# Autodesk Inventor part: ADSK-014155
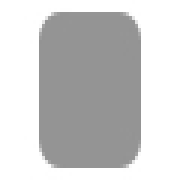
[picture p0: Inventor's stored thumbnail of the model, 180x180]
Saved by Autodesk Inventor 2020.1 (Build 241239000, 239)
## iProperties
Created: 2019-01
Part Number: ADSK-014155
Material: Stahl, weich
Document SubType Name: Modeling
Designer: lutzd
Language: de-DE
Size Designation: 5 x 39,384472 x 39,384472
Categories: <MemberInstance><Categories><Category DisplayName="Sonstige Bauteile" InternalName="5aa15e00-363f-49f2-933f-16f664388e3f" Mnemonic="OTHER"><Category DisplayName
Mass: 60.0398 g
Surface Area: 38.0412 cm^2
Volume: 7.64838 cm^3
Density: 7.85 g/cm^3
Appearance: Halbpoliert
Dimensions: 39,4x39,4x5 mm
Mass: 0,06 kg
DocNumber: ADSK-014155
Folder: 01 - Themengebiete\Simplification\01 - Packaging machine\
VDS_Category: 3D Komponenten
VDS_NumSchm: Autodesk
IsCustomPart: 1
Title: end cap
Author: lutzd
Revision Number: -
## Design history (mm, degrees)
sketch "Sketch1"
  geometry: L1 (0, 20.175)-(0, -21.446); L2 (-20.203, 0)-(20.169, 0); L3 (-19.692, 19.692)-(19.692, 19.692); L4 (19.692, 19.692)-(19.692, -19.692); L5 (19.692, -19.692)-(-19.692, -19.692); L6 (-19.692, -19.692)-(-19.692, 19.692); 1 further point
  constraints: 12 end point, 2 horizontal, 2 parallel, 2 point on line, 1 perpendicular, 1 vertical
  dimensions: "d0" = 39.38447 distance between parallel lines of L5 L3 (= height); "d1" = 19.69224 distance between parallel lines of L2 L3 (= 0.5 x height); "d2" = 39.38447 distance between parallel lines of L6 L4 (= width); "d3" = 19.69224 distance between parallel lines of L6 L1 (= 0.5 x width)
extrude "Extrusion1" new body sketch "Sketch1" distance "d4" = 5 (= thickness); taper "d5" = 0 deg
fillet "Fillet1" dims "d6" = 5 (= fillet), "d7" = 0, "fillet" = 5 [user parameter; used in 1 equation term]
chamfer "Chamfer1" distance "d8" = 0 (computed from chamfer); stored, may be unused: second distance "d9" = 2, angle "d10" = 45 deg; dims "d11" = 0, "chamfer" = 0 [user parameter; used in 1 equation term]
body "Solid1"
other parameters: "thickness" = 5 [user parameter; used in 1 equation term], "width" = 39.38447 [user parameter; used in 2 equation terms], "height" = 39.38447 [user parameter; used in 2 equation terms]
